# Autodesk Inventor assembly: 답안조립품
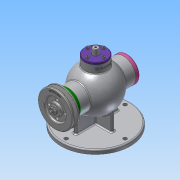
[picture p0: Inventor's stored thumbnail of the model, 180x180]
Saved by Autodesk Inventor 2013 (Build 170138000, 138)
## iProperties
Created: 2020-08
Part Number: 답안조립품
Document SubType Name: Assembly
Designer: user
Author: user
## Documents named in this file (18)
- C:\Users\user\Desktop\700806V1047\답안조립품.iam
- C:\Users\user\Desktop\700806V1047\본체.ipt
- C:\Users\user\Desktop\700806V1047\Ű 3x3x12.ipt
- C:\Users\user\Desktop\700806V1047\V-벨트풀리.ipt
- C:\Users\user\Desktop\700806V1047\너트 M8.ipt
- C:\Users\user\Desktop\700806V1047\뒤커버.ipt
- C:\Users\user\Desktop\700806V1047\멈춤링 15x1.ipt
- C:\Users\user\Desktop\700806V1047\멈춤링 35x1.6.ipt
- 멈춤링 35x1.6.ipt
- C:\Users\user\Desktop\700806V1047\베어링 6202.ipt
- 베어링 6202.ipt
- C:\Users\user\Desktop\700806V1047\볼트 M4.ipt
- C:\Users\user\Desktop\700806V1047\상부커버.ipt
- C:\Users\user\Desktop\700806V1047\슬라이드.ipt
- C:\Users\user\Desktop\700806V1047\앞커버.ipt
- C:\Users\user\Desktop\700806V1047\오일 실 15 30 7.ipt
- C:\Users\user\Desktop\700806V1047\칼라.ipt
- C:\Users\user\Desktop\700806V1047\편심축.ipt
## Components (2 placed, 2 different names)
1. Ű 3x3x12:1
2. V-벨트풀리:1
